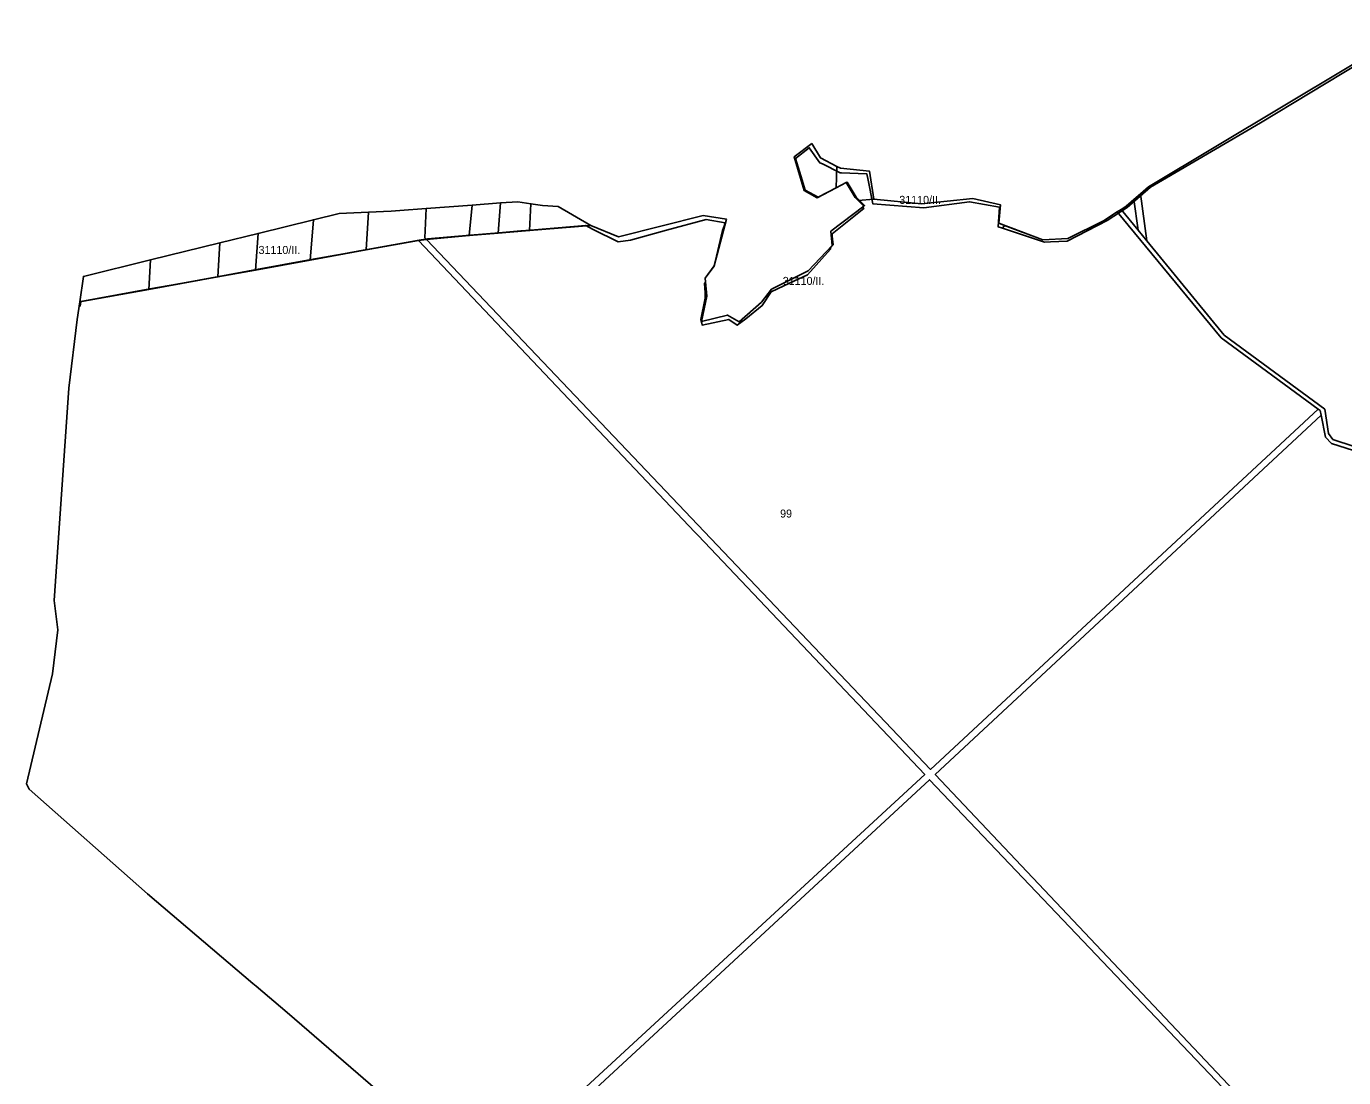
# Model space of a CAD drawing. Extents: x -535894 to -532834, y -1165802 to -1163645.
# Drawn here: x -535894 to -535071, y -1164561 to -1163904 of the extents above; entities that cross this region are included whole.
import ezdxf

# ---------------------------------------------------------------- set-up
doc = ezdxf.new("R2010")
doc.units = 0
for name, color, linetype in [('95590013', 7, 'Continuous'), ('95620013', 7, 'Continuous'), ('95640013', 7, 'Continuous'), ('95660013', 7, 'Continuous')]:
    doc.layers.add(name, color=color, linetype=linetype)

msp = doc.modelspace()

# ---------------------------------------------------------------- linework, layer by layer
at = {"layer": '95590013'}
for points in [[(-535598.07, -1164014.27), (-535599.52, -1164033.18), (-535617.54, -1164034.67), (-535615.79, -1164015.65)], [(-535587.24, -1164013.46), (-535579.04, -1164014.78), (-535579.83, -1164031.55), (-535599.52, -1164033.18), (-535598.07, -1164014.27)], [(-535680.43, -1164019.97), (-535682, -1164043.66), (-535716.94, -1164050.01), (-535714.97, -1164024.78), (-535698.8, -1164020.81)], [(-535644.41, -1164017.71), (-535645.29, -1164035.98), (-535644.3, -1164037.06), (-535649.36, -1164037.73), (-535682, -1164043.66), (-535680.43, -1164019.97), (-535666.39, -1164019.34), (-535661, -1164018.94)], [(-535615.79, -1164015.65), (-535617.54, -1164034.67), (-535644.3, -1164037.06), (-535645.29, -1164035.98), (-535644.41, -1164017.71)], [(-535571.78, -1164015.94), (-535561.92, -1164016.58), (-535541.53, -1164028.39), (-535579.83, -1164031.55), (-535579.04, -1164014.78)], [(-535714.97, -1164024.78), (-535716.94, -1164050.01), (-535751.06, -1164056.2), (-535749.49, -1164033.28)], [(-535773.53, -1164039.2), (-535774.61, -1164060.48), (-535817.82, -1164068.33), (-535816.78, -1164049.85)], [(-535749.49, -1164033.28), (-535751.06, -1164056.2), (-535774.61, -1164060.48), (-535773.53, -1164039.2)], [(-535816.78, -1164049.85), (-535817.82, -1164068.33), (-535860.97, -1164076.16), (-535858.66, -1164060.16)]]:
    msp.add_lwpolyline(points, close=True, dxfattribs=at)
at = {"layer": '95620013'}
for points in [[(-535037.17, -1164175.56), (-535077.79, -1164162.19), (-535080.49, -1164158.48), (-535082.87, -1164143.2), (-535145.65, -1164096.91), (-535194.06, -1164037.89), (-535198.09, -1164008.6), (-535193.05, -1164004.23), (-535025.69, -1163903.86)], [(-535117.95, -1164592.03), (-535326.28, -1164371.53), (-535085.14, -1164146.96), (-535082.44, -1164160.63), (-535078.73, -1164164.6), (-535038.07, -1164177.61)]]:
    msp.add_lwpolyline(points, dxfattribs=at)
for points in [[(-535403.43, -1163977.11), (-535398.02, -1163986.08), (-535387.79, -1163991.42), (-535388.33, -1164004.85), (-535400.04, -1164011.03), (-535408.16, -1164006.52), (-535414.57, -1163985.52)], [(-535385.61, -1163992.56), (-535367.36, -1163994.47), (-535364.66, -1164011.94), (-535374.4, -1164012.83), (-535376.31, -1164010.95), (-535381.95, -1164001.48), (-535388.33, -1164004.85), (-535387.79, -1163991.42)], [(-535364.66, -1164011.94), (-535335, -1164014.8), (-535302.8, -1164011.53), (-535285.57, -1164015.37), (-535286.58, -1164026.96), (-535259.04, -1164037.22), (-535243.35, -1164036.42), (-535221.22, -1164025.37), (-535212.54, -1164019.84), (-535147.62, -1164098.64), (-535086.95, -1164143.16), (-535329.29, -1164368.36), (-535644.3, -1164037.06), (-535617.54, -1164034.67), (-535599.52, -1164033.18), (-535579.83, -1164031.55), (-535541.53, -1164028.39), (-535524.35, -1164035.36), (-535471.34, -1164022.13), (-535456.81, -1164024.35), (-535464.43, -1164053.66), (-535470.22, -1164061.35), (-535469.11, -1164072.45), (-535472.32, -1164088.29), (-535456.22, -1164084.32), (-535448.87, -1164088.63), (-535434.91, -1164076.33), (-535428.61, -1164068.13), (-535405.71, -1164056.67), (-535390.72, -1164040.8), (-535391.51, -1164031.93), (-535370.99, -1164016.2), (-535374.4, -1164012.83)], [(-535202.21, -1164012.17), (-535199.44, -1164031.33), (-535210.13, -1164018.3), (-535206.91, -1164016.24)], [(-535649.36, -1164037.73), (-535476.52, -1164220.08), (-535474.5, -1164222.2), (-535332.86, -1164371.64), (-535608.87, -1164626.28), (-535731.43, -1164520.35), (-535750.75, -1164503.89), (-535752.85, -1164502.11), (-535818.64, -1164446.08), (-535892.52, -1164380.76), (-535894.37, -1164377.39), (-535877.94, -1164308.59), (-535874.71, -1164281.05), (-535877.05, -1164262.85), (-535867.9, -1164130.03), (-535862.54, -1164087.02), (-535860.97, -1164076.16), (-535817.82, -1164068.33), (-535774.61, -1164060.48), (-535751.06, -1164056.2), (-535716.94, -1164050.01), (-535682, -1164043.66)], [(-535644.3, -1164037.06), (-535329.29, -1164368.36), (-535086.95, -1164143.16), (-535085.71, -1164144.07), (-535085.14, -1164146.96), (-535326.28, -1164371.53), (-535117.95, -1164592.03), (-535121.76, -1164593.37), (-535329.84, -1164374.82), (-535605.04, -1164629.61), (-535608.87, -1164626.28), (-535332.86, -1164371.64), (-535474.5, -1164222.2), (-535476.52, -1164220.08), (-535649.36, -1164037.73)], [(-535121.76, -1164593.37), (-535124.4, -1164594.3), (-535157.57, -1164608.35), (-535174.63, -1164617.97), (-535226.37, -1164662.4), (-535265.14, -1164694.54), (-535274.36, -1164699.8), (-535299.42, -1164711.94), (-535322.24, -1164718.04), (-535337.8, -1164722.86), (-535434.81, -1164774.69), (-535538.55, -1164687.07), (-535605.04, -1164629.61), (-535329.84, -1164374.82)]]:
    msp.add_lwpolyline(points, close=True, dxfattribs=at)
at = {"layer": '95640013'}
msp.add_lwpolyline([(-535198.09, -1164008.6), (-535194.06, -1164037.89), (-535199.44, -1164031.33), (-535202.21, -1164012.17)], close=True, dxfattribs=at)
msp.add_lwpolyline([(-535038.07, -1164177.61), (-535078.73, -1164164.6), (-535082.44, -1164160.63), (-535085.14, -1164146.96), (-535085.71, -1164144.07), (-535086.95, -1164143.16), (-535147.62, -1164098.64), (-535212.54, -1164019.84), (-535210.13, -1164018.3), (-535199.44, -1164031.33), (-535194.06, -1164037.89), (-535145.65, -1164096.91), (-535082.87, -1164143.2), (-535080.49, -1164158.48), (-535077.79, -1164162.19), (-535037.17, -1164175.56)], dxfattribs=at)
at = {"layer": '95660013'}
for points in [[(-535060.95, -1163926.6), (-535123.09, -1163964.15), (-535184.283, -1164000), (-535191.879, -1164004.45), (-535206.27, -1164017.13), (-535218.879, -1164025.24), (-535243.809, -1164038.08), (-535254.323, -1164038.581), (-535257.966, -1164038.797), (-535284.325, -1164030.09), (-535284.14, -1164029.836), (-535283.01, -1164028.29), (-535259.04, -1164037.22), (-535243.35, -1164036.42), (-535221.22, -1164025.37), (-535212.54, -1164019.84), (-535210.13, -1164018.3), (-535206.91, -1164016.24), (-535202.21, -1164012.17), (-535198.09, -1164008.6), (-535193.05, -1164004.23), (-535025.69, -1163903.86)], [(-535608.87, -1164626.28), (-535731.43, -1164520.35), (-535750.75, -1164503.89), (-535752.85, -1164502.11), (-535818.64, -1164446.08), (-535892.52, -1164380.76), (-535894.37, -1164377.39), (-535877.94, -1164308.59), (-535874.71, -1164281.05), (-535877.05, -1164262.85), (-535867.9, -1164130.03), (-535862.54, -1164087.02), (-535861.354, -1164078.82), (-535860.832, -1164078.707), (-535860.42, -1164075.851), (-535817.263, -1164068.017), (-535799.13, -1164064.723), (-535774.102, -1164060.177), (-535774.054, -1164060.168), (-535750.51, -1164055.897), (-535716.39, -1164049.703), (-535696.084, -1164046.016), (-535683.928, -1164043.81), (-535681.446, -1164043.359), (-535648.804, -1164037.434), (-535643.748, -1164036.759), (-535616.982, -1164034.374), (-535598.97, -1164032.888), (-535585.382, -1164031.761), (-535579.28, -1164031.255), (-535552.117, -1164029.012), (-535544.813, -1164028.409), (-535544.696, -1164028.399), (-535542.809, -1164029.44), (-535540.105, -1164030.779), (-535524.399, -1164038.55), (-535516.73, -1164037.45), (-535494.317, -1164031.21), (-535469.421, -1164024.672), (-535457.62, -1164026.594), (-535457.976, -1164028.066), (-535459.219, -1164031.44), (-535464.556, -1164053.828), (-535470.22, -1164061.35), (-535469.981, -1164063.742), (-535470.62, -1164064.63), (-535470.176, -1164070.177), (-535470.176, -1164073.747), (-535472.784, -1164087.2), (-535472.448, -1164089.047), (-535472.097, -1164089.102), (-535472.09, -1164090.59), (-535455.399, -1164087.06), (-535450.099, -1164090.67), (-535444.6, -1164086.66), (-535434.39, -1164078.45), (-535428.91, -1164069.77), (-535417.399, -1164064.36), (-535406.09, -1164059.25), (-535391.809, -1164043.17), (-535391.84, -1164042.287), (-535390.168, -1164040.516), (-535390.655, -1164035.023), (-535390.789, -1164033.504), (-535370.899, -1164017.75), (-535371.884, -1164017.027), (-535370.441, -1164015.92), (-535373.849, -1164012.543), (-535375.752, -1164010.661), (-535381.401, -1164001.199), (-535381.946, -1164001.486), (-535381.95, -1164001.48), (-535388.33, -1164004.85), (-535399.494, -1164010.742), (-535407.605, -1164006.231), (-535409.51, -1164000), (-535413.67, -1163986.392), (-535405.065, -1163979.77), (-535398.479, -1163989.104), (-535396.874, -1163989.857), (-535385.71, -1163995.36), (-535385.116, -1163995.378), (-535385.031, -1163995.419), (-535369.114, -1163995.968), (-535368.296, -1164000), (-535365.272, -1164014.912), (-535333.437, -1164017.383), (-535304.895, -1164013.539), (-535286.233, -1164016.834), (-535287.057, -1164029.188), (-535284.325, -1164030.09), (-535257.966, -1164038.797), (-535254.323, -1164038.581), (-535243.809, -1164038.08), (-535218.879, -1164025.24), (-535206.27, -1164017.13), (-535191.879, -1164004.45), (-535184.283, -1164000), (-535123.09, -1163964.15), (-535060.95, -1163926.6)]]:
    msp.add_lwpolyline(points, dxfattribs=at)
for points in [[(-535403.43, -1163977.11), (-535398.02, -1163986.08), (-535387.79, -1163991.42), (-535385.61, -1163992.56), (-535367.36, -1163994.47), (-535364.66, -1164011.94), (-535335, -1164014.8), (-535302.8, -1164011.53), (-535285.57, -1164015.37), (-535286.58, -1164026.96), (-535283.01, -1164028.29), (-535284.14, -1164029.836), (-535284.325, -1164030.09), (-535287.057, -1164029.188), (-535286.233, -1164016.834), (-535304.895, -1164013.539), (-535333.437, -1164017.383), (-535365.272, -1164014.912), (-535368.296, -1164000), (-535369.114, -1163995.968), (-535385.031, -1163995.419), (-535385.116, -1163995.378), (-535385.71, -1163995.36), (-535396.874, -1163989.857), (-535398.479, -1163989.104), (-535405.065, -1163979.77), (-535413.67, -1163986.392), (-535409.51, -1164000), (-535407.605, -1164006.231), (-535399.494, -1164010.742), (-535400.04, -1164011.03), (-535408.16, -1164006.52), (-535414.57, -1163985.52)], [(-535444.6, -1164086.66), (-535450.099, -1164090.67), (-535455.399, -1164087.06), (-535472.09, -1164090.59), (-535472.097, -1164089.102), (-535472.448, -1164089.047), (-535472.784, -1164087.2), (-535470.176, -1164073.747), (-535470.176, -1164070.177), (-535470.62, -1164064.63), (-535469.981, -1164063.742), (-535469.11, -1164072.45), (-535472.32, -1164088.29), (-535456.22, -1164084.32), (-535448.87, -1164088.63), (-535434.91, -1164076.33), (-535428.61, -1164068.13), (-535405.71, -1164056.67), (-535390.72, -1164040.8), (-535391.51, -1164031.93), (-535370.99, -1164016.2), (-535374.4, -1164012.83), (-535376.31, -1164010.95), (-535381.946, -1164001.486), (-535381.401, -1164001.199), (-535375.752, -1164010.661), (-535373.849, -1164012.543), (-535370.441, -1164015.92), (-535371.884, -1164017.027), (-535370.899, -1164017.75), (-535390.789, -1164033.504), (-535390.655, -1164035.023), (-535390.168, -1164040.516), (-535391.84, -1164042.287), (-535391.809, -1164043.17), (-535406.09, -1164059.25), (-535417.399, -1164064.36), (-535428.91, -1164069.77), (-535434.39, -1164078.45)], [(-535541.53, -1164028.39), (-535524.35, -1164035.36), (-535471.34, -1164022.13), (-535456.81, -1164024.35), (-535464.43, -1164053.66), (-535464.556, -1164053.828), (-535459.219, -1164031.44), (-535457.976, -1164028.066), (-535457.62, -1164026.594), (-535469.421, -1164024.672), (-535494.317, -1164031.21), (-535516.73, -1164037.45), (-535524.399, -1164038.55), (-535540.105, -1164030.779), (-535542.809, -1164029.44), (-535544.696, -1164028.399), (-535544.813, -1164028.409), (-535552.117, -1164029.012), (-535579.28, -1164031.255), (-535585.382, -1164031.761), (-535598.97, -1164032.888), (-535616.982, -1164034.374), (-535643.748, -1164036.759), (-535648.804, -1164037.434), (-535681.446, -1164043.359), (-535683.928, -1164043.81), (-535696.084, -1164046.016), (-535716.39, -1164049.703), (-535750.51, -1164055.897), (-535774.054, -1164060.168), (-535774.102, -1164060.177), (-535799.13, -1164064.723), (-535817.263, -1164068.017), (-535860.42, -1164075.851), (-535860.832, -1164078.707), (-535861.354, -1164078.82), (-535860.97, -1164076.16), (-535858.66, -1164060.16), (-535816.78, -1164049.85), (-535773.53, -1164039.2), (-535749.49, -1164033.28), (-535714.97, -1164024.78), (-535698.8, -1164020.81), (-535680.43, -1164019.97), (-535666.39, -1164019.34), (-535661, -1164018.94), (-535644.41, -1164017.71), (-535615.79, -1164015.65), (-535598.07, -1164014.27), (-535587.24, -1164013.46), (-535579.04, -1164014.78), (-535571.78, -1164015.94), (-535561.92, -1164016.58)]]:
    msp.add_lwpolyline(points, close=True, dxfattribs=at)

# ---------------------------------------------------------------- texts
for s, rotation, p in [('31110/II.', 0, (-535348.79, -1164014.831)), ('31110/II.', 0, (-535749.24, -1164046.14)), ('31110/II.', 360, (-535421.612, -1164065.484)), ('99', 360, (-535423.272, -1164210.923))]:
    msp.add_text(s, height=5, rotation=rotation, dxfattribs=at).set_placement(p)

doc.saveas('drawing.dxf')
